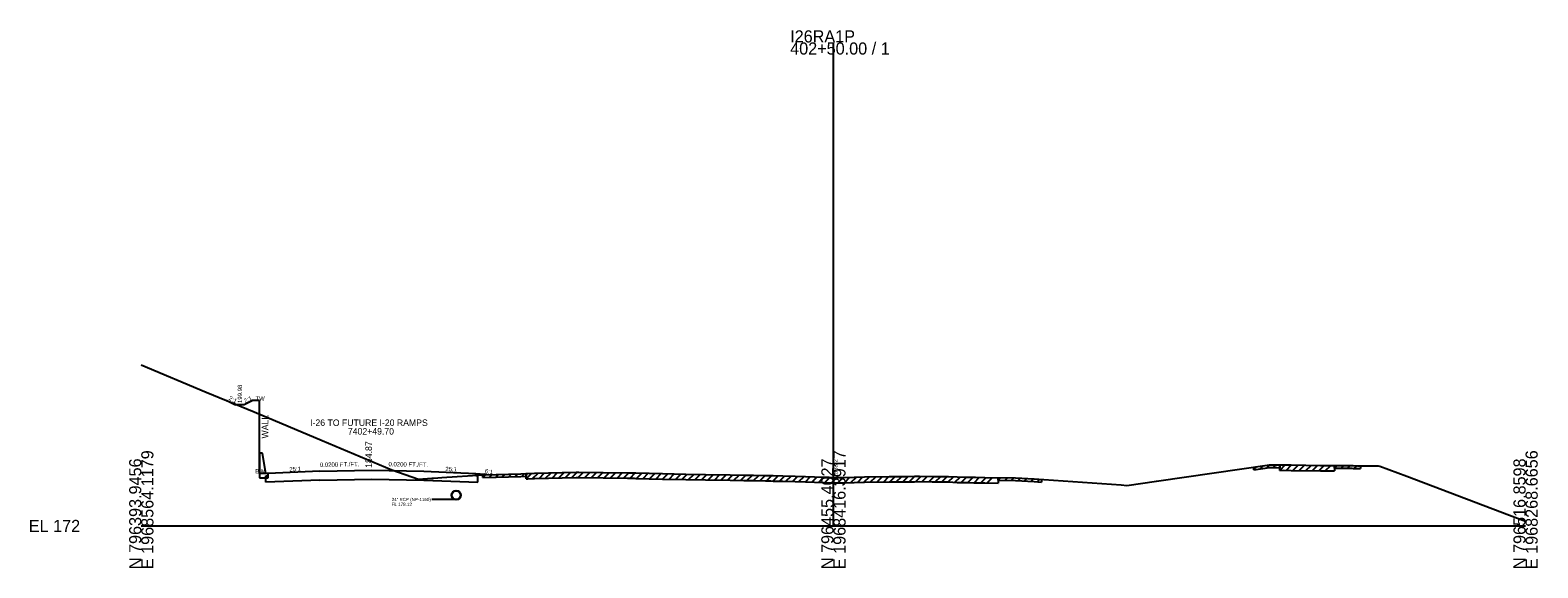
# Model space of a CAD drawing. Extents: x -44 to 4323, y -10 to 9601.
# Drawn here: x -25.7 to 322.8, y 1490.3 to 1614.6 of the extents above; entities that cross this region are included whole.
import ezdxf

# ---------------------------------------------------------------- set-up
doc = ezdxf.new("R2010")
doc.units = 0
for name, color, linetype in [('1', 7, 'Continuous'), ('DateStamp', 7, 'Continuous'), ('NotForConst', 7, 'Continuous'), ('RD_SHT_Bndy', 7, 'Continuous'), ('RD_SHT_Iplotshp', 7, 'Continuous'), ('RD_SHT_TX', 7, 'Continuous'), ('RD_Sketch10', 7, 'Continuous'), ('RD_XS_ExGround', 7, 'Continuous'), ('RD_XS_ExPaveRet', 7, 'Continuous'), ('RD_XS_MatchLine', 7, 'Continuous'), ('RD_XS_Misc_Line', 7, 'Continuous'), ('RD_XS_Pave', 7, 'Continuous'), ('RD_XS_PaveShd', 7, 'Continuous'), ('RD_XS_Pipe', 7, 'Continuous'), ('RD_XS_TX_Elev_PR', 7, 'Continuous'), ('RD_XS_TX_ShdSlope', 7, 'Continuous'), ('RD_XS_TX_Slope', 7, 'Continuous'), ('seal', 7, 'Continuous'), ('TR SN EXTRUDED PANEL SIGNS - GROUND MOUNTED', 7, 'Continuous')]:
    doc.layers.add(name, color=color, linetype=linetype)

msp = doc.modelspace()

# ---------------------------------------------------------------- linework, layer by layer
at = {"layer": 'DateStamp'}
msp.add_lwpolyline([(0, 1537.26), (14.97, 1530.94), (26.12, 1526.41), (41.79, 1519.78), (57.93, 1512.96), (64.05, 1510.81), (67.16, 1511.02), (67.62, 1511.05), (69.51, 1511.18), (78.95, 1511.82), (82.06, 1511.9), (87.77, 1512.08), (88.93, 1512.14), (89.37, 1512.16), (90.9, 1512.2), (100.52, 1512.42), (101.11, 1512.42), (112.4, 1512.3), (113.47, 1512.27), (113.95, 1512.26), (114.32, 1512.25), (120.52, 1512.09), (125.87, 1511.97), (130.43, 1511.88), (136.11, 1511.84), (139.26, 1511.73), (140.1, 1511.72), (141.54, 1511.72), (144.27, 1511.66), (145.53, 1511.64), (146.05, 1511.63), (148.32, 1511.58), (151.19, 1511.51), (153.57, 1511.45), (157.71, 1511.29), (159.04, 1511.24), (160, 1511.22), (161.37, 1511.2), (161.75, 1511.19), (162.43, 1511.21), (167.18, 1511.35), (172.9, 1511.41), (177.19, 1511.44), (178.71, 1511.48), (179.87, 1511.52), (182.81, 1511.45), (184.29, 1511.41), (184.86, 1511.43), (185.68, 1511.45), (186.62, 1511.41), (188.63, 1511.32), (190.61, 1511.28), (191.32, 1511.27), (192.45, 1511.25), (192.88, 1511.25), (194.97, 1511.22), (202.12, 1511.11), (206.43, 1510.88), (226.51, 1509.47), (227.81, 1509.34), (234.71, 1510.36), (260.8, 1514.16), (261.4, 1514.14), (262.54, 1514.12), (263.19, 1514.1), (264.01, 1514.11), (265.82, 1514.09), (272.6, 1513.98), (275.59, 1513.97), (279.85, 1513.94), (280.17, 1513.94), (281.15, 1513.92), (285.05, 1513.88), (285.89, 1513.87), (286.33, 1513.84), (292.52, 1511.5), (316.3, 1502.52), (320, 1501.11)], dxfattribs=at)
at = {"layer": 'NotForConst'}
for p, q in [((257.16, 1513), (257.9, 1513.73)), ((258.66, 1513.22), (259.4, 1513.95)), ((260.17, 1513.44), (260.88, 1514.15)), ((261.67, 1513.51), (262.28, 1514.12)), ((263.19, 1512.85), (264.45, 1514.11)), ((264.69, 1512.85), (265.93, 1514.09)), ((266.2, 1512.83), (267.43, 1514.06)), ((267.7, 1512.81), (268.93, 1514.04)), ((269.2, 1512.78), (270.43, 1514.01)), ((270.7, 1512.76), (271.93, 1513.99)), ((272.2, 1512.74), (273.44, 1513.98)), ((273.7, 1512.72), (274.95, 1513.97)), ((275.84, 1513.34), (276.46, 1513.96)), ((277.34, 1513.33), (277.96, 1513.95)), ((278.84, 1513.32), (279.46, 1513.94)), ((280.34, 1513.31), (280.96, 1513.92)), ((78.95, 1511.19), (79.59, 1511.83)), ((80.45, 1511.23), (81.09, 1511.87)), ((81.95, 1511.27), (82.59, 1511.92)), ((83.45, 1511.32), (84.1, 1511.96)), ((84.95, 1511.37), (85.6, 1512.01)), ((86.45, 1511.41), (87.1, 1512.06)), ((87.95, 1511.46), (88.62, 1512.12)), ((88.96, 1510.89), (90.25, 1512.19)), ((90.46, 1510.94), (91.74, 1512.22)), ((91.96, 1510.98), (93.24, 1512.26)), ((93.46, 1511.01), (94.74, 1512.29)), ((94.96, 1511.05), (96.24, 1512.32)), ((96.46, 1511.08), (97.74, 1512.36)), ((97.96, 1511.11), (99.25, 1512.39)), ((99.47, 1511.15), (100.74, 1512.42)), ((100.97, 1511.17), (102.21, 1512.4)), ((102.47, 1511.15), (103.71, 1512.39)), ((103.97, 1511.14), (105.21, 1512.37)), ((105.47, 1511.12), (106.71, 1512.36)), ((106.97, 1511.11), (108.21, 1512.35)), ((108.47, 1511.09), (109.71, 1512.33)), ((109.98, 1511.08), (111.22, 1512.32)), ((111.48, 1511.06), (112.71, 1512.29)), ((112.98, 1511.03), (114.2, 1512.25)), ((114.48, 1510.99), (115.7, 1512.21)), ((115.98, 1510.95), (117.2, 1512.17)), ((117.48, 1510.92), (118.7, 1512.14)), ((118.99, 1510.88), (120.21, 1512.1)), ((120.49, 1510.84), (121.71, 1512.06)), ((121.99, 1510.81), (123.21, 1512.03)), ((123.49, 1510.77), (124.71, 1512)), ((124.99, 1510.74), (126.22, 1511.96)), ((126.49, 1510.71), (127.72, 1511.93)), ((127.99, 1510.68), (129.22, 1511.9)), ((129.5, 1510.65), (130.73, 1511.88)), ((131, 1510.62), (132.24, 1511.87)), ((132.5, 1510.61), (133.74, 1511.86)), ((134, 1510.6), (135.24, 1511.85)), ((135.5, 1510.59), (136.73, 1511.82)), ((137, 1510.56), (138.21, 1511.76)), ((138.5, 1510.5), (139.72, 1511.72)), ((140.01, 1510.47), (141.26, 1511.72)), ((141.51, 1510.47), (142.73, 1511.69)), ((143.01, 1510.44), (144.23, 1511.66)), ((144.51, 1510.4), (145.74, 1511.63)), ((146.01, 1510.38), (147.24, 1511.61)), ((147.51, 1510.35), (148.74, 1511.57)), ((149.01, 1510.32), (150.23, 1511.53)), ((150.52, 1510.28), (151.74, 1511.5)), ((152.02, 1510.24), (153.24, 1511.46)), ((153.52, 1510.2), (154.72, 1511.41)), ((155.02, 1510.14), (156.22, 1511.35)), ((156.52, 1510.08), (157.72, 1511.29)), ((158.02, 1510.03), (159.24, 1511.24)), ((159.52, 1509.98), (160.75, 1511.21)), ((161.03, 1509.95), (162.28, 1511.2)), ((162.53, 1509.96), (163.82, 1511.25)), ((164.03, 1510.01), (165.32, 1511.29)), ((165.53, 1510.05), (166.82, 1511.34)), ((167.03, 1510.09), (168.3, 1511.36)), ((168.53, 1510.11), (169.8, 1511.38)), ((170.03, 1510.13), (171.3, 1511.39)), ((171.54, 1510.14), (172.8, 1511.41)), ((173.04, 1510.16), (174.3, 1511.42)), ((174.54, 1510.17), (175.8, 1511.43)), ((176.04, 1510.18), (177.3, 1511.45)), ((177.54, 1510.2), (178.83, 1511.49)), ((179.04, 1510.24), (180.31, 1511.51)), ((180.55, 1510.25), (181.77, 1511.47)), ((182.05, 1510.22), (183.27, 1511.43)), ((183.55, 1510.18), (184.8, 1511.43)), ((185.05, 1510.18), (186.29, 1511.42)), ((186.55, 1510.16), (187.75, 1511.36)), ((188.05, 1510.09), (189.27, 1511.31)), ((189.55, 1510.05), (190.78, 1511.28)), ((191.06, 1510.02), (192.29, 1511.25)), ((192.56, 1510), (193.79, 1511.24)), ((194.06, 1509.98), (195.29, 1511.21)), ((195.56, 1509.96), (196.79, 1511.19)), ((198.12, 1510.55), (198.73, 1511.16)), ((199.62, 1510.52), (200.23, 1511.14)), ((201.12, 1510.5), (201.74, 1511.12)), ((202.62, 1510.46), (203.21, 1511.05)), ((204.12, 1510.38), (204.71, 1510.97)), ((205.62, 1510.29), (206.22, 1510.89)), ((207.12, 1510.2), (207.71, 1510.79))]:
    msp.add_line(p, q, dxfattribs=at)
at = {"layer": 'RD_SHT_Bndy'}
for p, q in [((160, 1500), (160, 1611.79)), ((0, 1500), (160, 1500)), ((160, 1500), (320, 1500))]:
    msp.add_line(p, q, dxfattribs=at)
at = {"layer": 'RD_SHT_Iplotshp'}
for p, q in [((257.16, 1513), (257.16, 1513.63)), ((257.16, 1513), (260.8, 1513.53)), ((260.8, 1513.53), (261.4, 1513.51)), ((261.4, 1513.51), (262.54, 1513.49)), ((262.54, 1513.49), (263.19, 1513.47)), ((263.19, 1512.85), (263.19, 1514.1)), ((263.19, 1514.1), (263.19, 1513.47)), ((263.19, 1512.85), (264.01, 1512.86)), ((264.01, 1512.86), (265.82, 1512.84)), ((265.82, 1512.84), (272.6, 1512.73)), ((272.6, 1512.73), (275.59, 1512.72)), ((275.59, 1512.72), (275.84, 1512.71)), ((275.84, 1513.96), (275.84, 1512.71)), ((275.84, 1513.34), (275.84, 1513.96)), ((275.84, 1513.34), (279.85, 1513.32)), ((279.85, 1513.32), (280.17, 1513.31)), ((280.17, 1513.31), (281.15, 1513.29)), ((281.15, 1513.29), (281.87, 1513.29)), ((281.87, 1513.91), (281.87, 1513.29)), ((78.95, 1511.19), (78.95, 1511.82)), ((78.95, 1511.19), (82.06, 1511.28)), ((82.06, 1511.28), (87.77, 1511.45)), ((87.77, 1511.45), (88.93, 1511.51)), ((88.93, 1511.51), (88.96, 1511.52)), ((88.96, 1510.89), (88.96, 1512.14)), ((88.96, 1512.14), (88.96, 1511.52)), ((88.96, 1510.89), (89.37, 1510.91)), ((89.37, 1510.91), (90.9, 1510.95)), ((90.9, 1510.95), (100.52, 1511.17)), ((100.52, 1511.17), (101.11, 1511.17)), ((101.11, 1511.17), (112.4, 1511.05)), ((112.4, 1511.05), (113.47, 1511.02)), ((113.47, 1511.02), (113.95, 1511.01)), ((113.95, 1511.01), (114.32, 1511)), ((114.32, 1511), (120.52, 1510.84)), ((120.52, 1510.84), (125.87, 1510.72)), ((125.87, 1510.72), (130.43, 1510.63)), ((130.43, 1510.63), (136.11, 1510.59)), ((136.11, 1510.59), (139.26, 1510.48)), ((139.26, 1510.48), (140.1, 1510.47)), ((140.1, 1510.47), (141.54, 1510.47)), ((141.54, 1510.47), (144.27, 1510.41)), ((144.27, 1510.41), (145.53, 1510.39)), ((145.53, 1510.39), (146.05, 1510.38)), ((146.05, 1510.38), (148.32, 1510.33)), ((148.32, 1510.33), (151.19, 1510.26)), ((151.19, 1510.26), (153.57, 1510.2)), ((153.57, 1510.2), (157.71, 1510.04)), ((157.71, 1510.04), (159.04, 1509.99)), ((159.04, 1509.99), (160, 1509.97)), ((160, 1509.97), (161.37, 1509.95)), ((161.37, 1509.95), (161.75, 1509.94)), ((161.75, 1509.94), (162.43, 1509.96)), ((162.43, 1509.96), (167.18, 1510.1)), ((167.18, 1510.1), (172.9, 1510.16)), ((172.9, 1510.16), (177.19, 1510.19)), ((177.19, 1510.19), (178.71, 1510.23)), ((178.71, 1510.23), (179.87, 1510.27)), ((179.87, 1510.27), (182.81, 1510.2)), ((182.81, 1510.2), (184.29, 1510.16)), ((184.29, 1510.16), (184.86, 1510.18)), ((184.86, 1510.18), (185.68, 1510.2)), ((185.68, 1510.2), (186.62, 1510.16)), ((186.62, 1510.16), (188.63, 1510.07)), ((188.63, 1510.07), (190.61, 1510.03)), ((190.61, 1510.03), (191.32, 1510.02)), ((191.32, 1510.02), (192.45, 1510)), ((192.45, 1510), (192.88, 1510)), ((192.88, 1510), (194.97, 1509.97)), ((194.97, 1509.97), (198.12, 1509.92)), ((198.12, 1511.17), (198.12, 1509.92)), ((198.12, 1510.55), (198.12, 1511.17)), ((198.12, 1510.55), (202.12, 1510.49)), ((202.12, 1510.49), (206.43, 1510.25)), ((206.43, 1510.25), (208.13, 1510.13)), ((208.13, 1510.76), (208.13, 1510.13))]:
    msp.add_line(p, q, dxfattribs=at)
at = {"layer": 'RD_XS_ExPaveRet'}
for p, q in [((27.3, 1512.15), (27.3, 1528.98)), ((29.3, 1512.15), (27.3, 1512.15))]:
    msp.add_line(p, q, dxfattribs=at)
at = {"layer": 'RD_XS_Misc_Line'}
for p, q in [((28.8, 1511.57), (29.3, 1511.59)), ((28.8, 1510.09), (28.8, 1511.57)), ((41.31, 1510.59), (28.8, 1510.09)), ((29.3, 1511.59), (29.3, 1512.15)), ((41.31, 1510.59), (53.31, 1510.83)), ((53.31, 1510.83), (65.31, 1510.59)), ((65.31, 1510.59), (77.82, 1510.09)), ((77.31, 1511.59), (77.31, 1512.15)), ((77.82, 1511.57), (77.31, 1511.59)), ((77.82, 1510.09), (77.82, 1511.57))]:
    msp.add_line(p, q, dxfattribs=at)
at = {"layer": 'RD_XS_Pave'}
msp.add_line((79.92, 1511.84), (79.32, 1511.99), dxfattribs=at)
at = {"layer": 'RD_XS_PaveShd'}
for p, q in [((19.8, 1528.98), (21.8, 1527.98)), ((23.8, 1527.98), (21.8, 1527.98)), ((25.8, 1528.98), (23.8, 1527.98)), ((27.3, 1528.98), (25.8, 1528.98)), ((77.31, 1512.15), (79.32, 1511.99))]:
    msp.add_line(p, q, dxfattribs=at)
at = {"layer": 'RD_XS_Pipe'}
msp.add_line((72.14, 1506.12), (67.14, 1506.12), dxfattribs=at)
for radius in [1.1, 1]:
    msp.add_circle((72.8, 1507.12), radius, dxfattribs=at)
at = {"layer": 'RD_XS_TX_Elev_PR'}
for p, q in [((41.31, 1512.63), (29.3, 1512.15)), ((65.31, 1512.63), (77.31, 1512.15))]:
    msp.add_line(p, q, dxfattribs=at)
at = {"layer": 'RD_XS_TX_ShdSlope'}
for p, q in [((28.05, 1516.82), (27.3, 1516.82)), ((27.3, 1516.82), (27.3, 1511.15)), ((28.8, 1512.15), (28.05, 1516.82)), ((27.3, 1511.15), (29.3, 1511.15)), ((29.3, 1512.15), (28.8, 1512.15)), ((29.3, 1511.15), (29.3, 1512.15))]:
    msp.add_line(p, q, dxfattribs=at)
at = {"layer": 'RD_XS_TX_Slope'}
for p, q in [((41.31, 1512.63), (53.31, 1512.87)), ((53.31, 1512.87), (65.31, 1512.63))]:
    msp.add_line(p, q, dxfattribs=at)

# ---------------------------------------------------------------- texts
at = {"layer": '1'}
for s, p in [('I-26 TO FUTURE I-20 RAMPS', (39.03, 1523.12)), ('7402+49.70', (47.76, 1521.12))]:
    msp.add_text(s, height=1.5, dxfattribs=at).set_placement(p)
at = {"layer": 'RD_SHT_Bndy'}
for s, p in [('I26RA1P', (150, 1611.79)), ('402+50.00 / 1', (150, 1608.99)), ('EL 172', (-26, 1498.6))]:
    msp.add_text(s, height=2.8, dxfattribs=at).set_placement(p)
for s, p in [('E 1968564.1179', (2.8, 1490)), ('E 1968416.3917', (162.8, 1490)), ('E 1968268.6656', (322.8, 1490)), ('N 796393.9456', (0, 1490)), ('N 796455.4027', (160, 1490)), ('N 796516.8598', (320, 1490))]:
    msp.add_text(s, height=2.8, rotation=90, dxfattribs=at).set_placement(p)
at = {"layer": 'RD_SHT_TX'}
msp.add_text('183.22', height=1, rotation=90, dxfattribs=at).set_placement((161, 1511.22))
at = {"layer": 'RD_Sketch10'}
for s, p in [('TW', (26.39, 1528.98)), ('BW', (26.32, 1512.15))]:
    msp.add_text(s, height=1, dxfattribs=at).set_placement(p)
at = {"layer": 'RD_XS_ExGround'}
for rotation, p in [(2.29, (34.24, 1512.6)), (357.71, (70.27, 1512.69))]:
    msp.add_text('25:1', height=1, rotation=rotation, dxfattribs=at).set_placement(p)
at = {"layer": 'RD_XS_MatchLine'}
msp.add_text('WALL', height=1.5, rotation=90, dxfattribs=at).set_placement((29.35, 1520.22))
at = {"layer": 'RD_XS_Pipe'}
for s, p in [('24" RCP (NP-1160)', (57.88, 1505.74)), ('FL 178.12', (57.88, 1504.62))]:
    msp.add_text(s, height=0.75, dxfattribs=at).set_placement(p)
at = {"layer": 'seal'}
msp.add_text(' 184.87', height=1.5, rotation=90, dxfattribs=at).set_placement((53.31, 1512.87))
at = {"layer": 'TR SN EXTRUDED PANEL SIGNS - GROUND MOUNTED'}
for s, rotation, p in [('199.98', 90, (23.3, 1528.42)), ('2:1', 333.4349, (20.11, 1529.19)), ('2:1', 26.5651, (24, 1528.36)), ('0.0200 FT./FT.', 1.1448, (41.29, 1513.63)), ('0.0200 FT./FT.', 358.8545, (57.14, 1513.8)), ('6:1', 350.5377, (79.35, 1512.25))]:
    msp.add_text(s, height=1, rotation=rotation, dxfattribs=at).set_placement(p)

doc.saveas('drawing.dxf')
